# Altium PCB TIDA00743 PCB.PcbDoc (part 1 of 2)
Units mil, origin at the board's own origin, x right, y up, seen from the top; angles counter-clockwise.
Board outline 2110 x 1665 mil, 6 copper layers (Layer 1 - Top Layer, Layer 2 - GND, Layer 3 - Sensitive, Layer 4 - PWR, Layer 5 - GND, Layer 6 - Bottom Layer), stack 59.268 mil thick; 144 components, 87 nets, 420 pads, 309 vias.
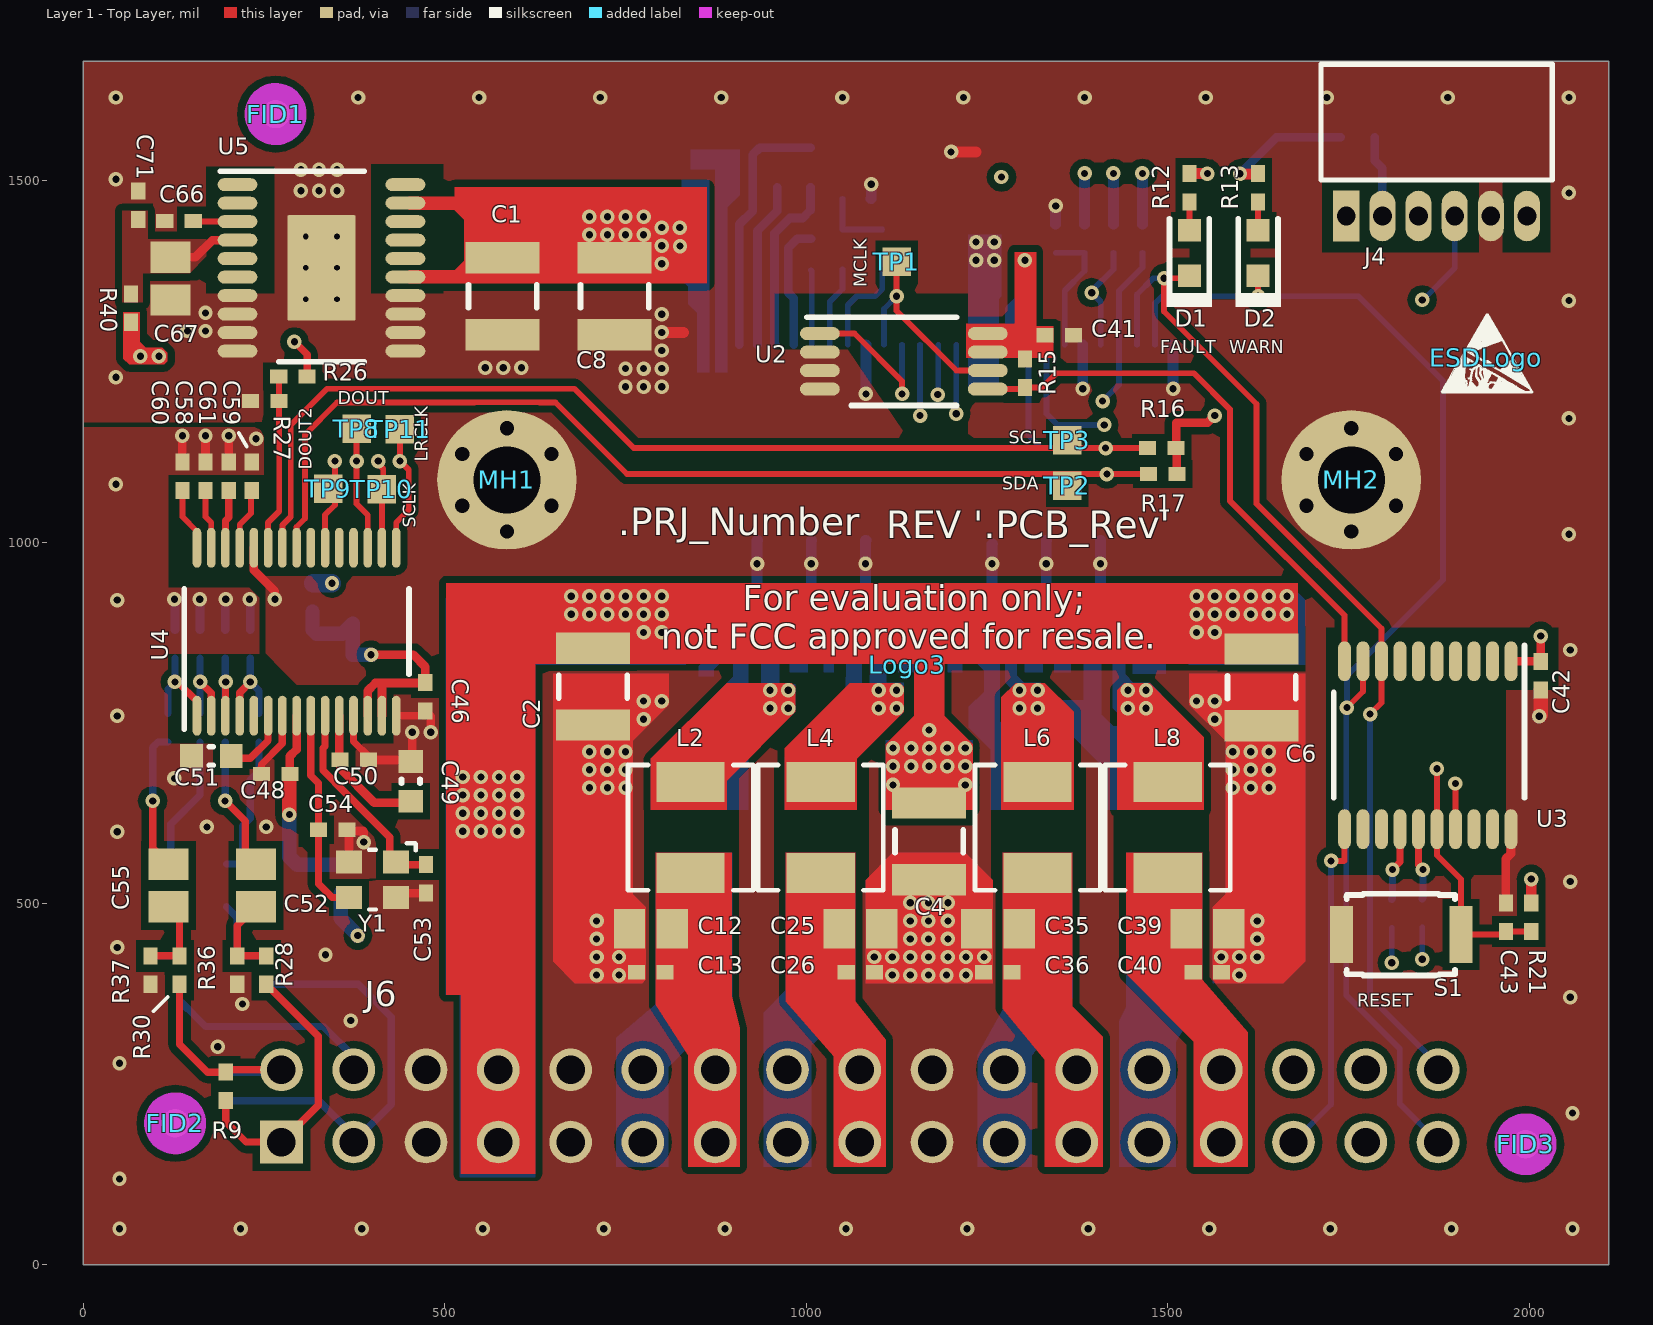
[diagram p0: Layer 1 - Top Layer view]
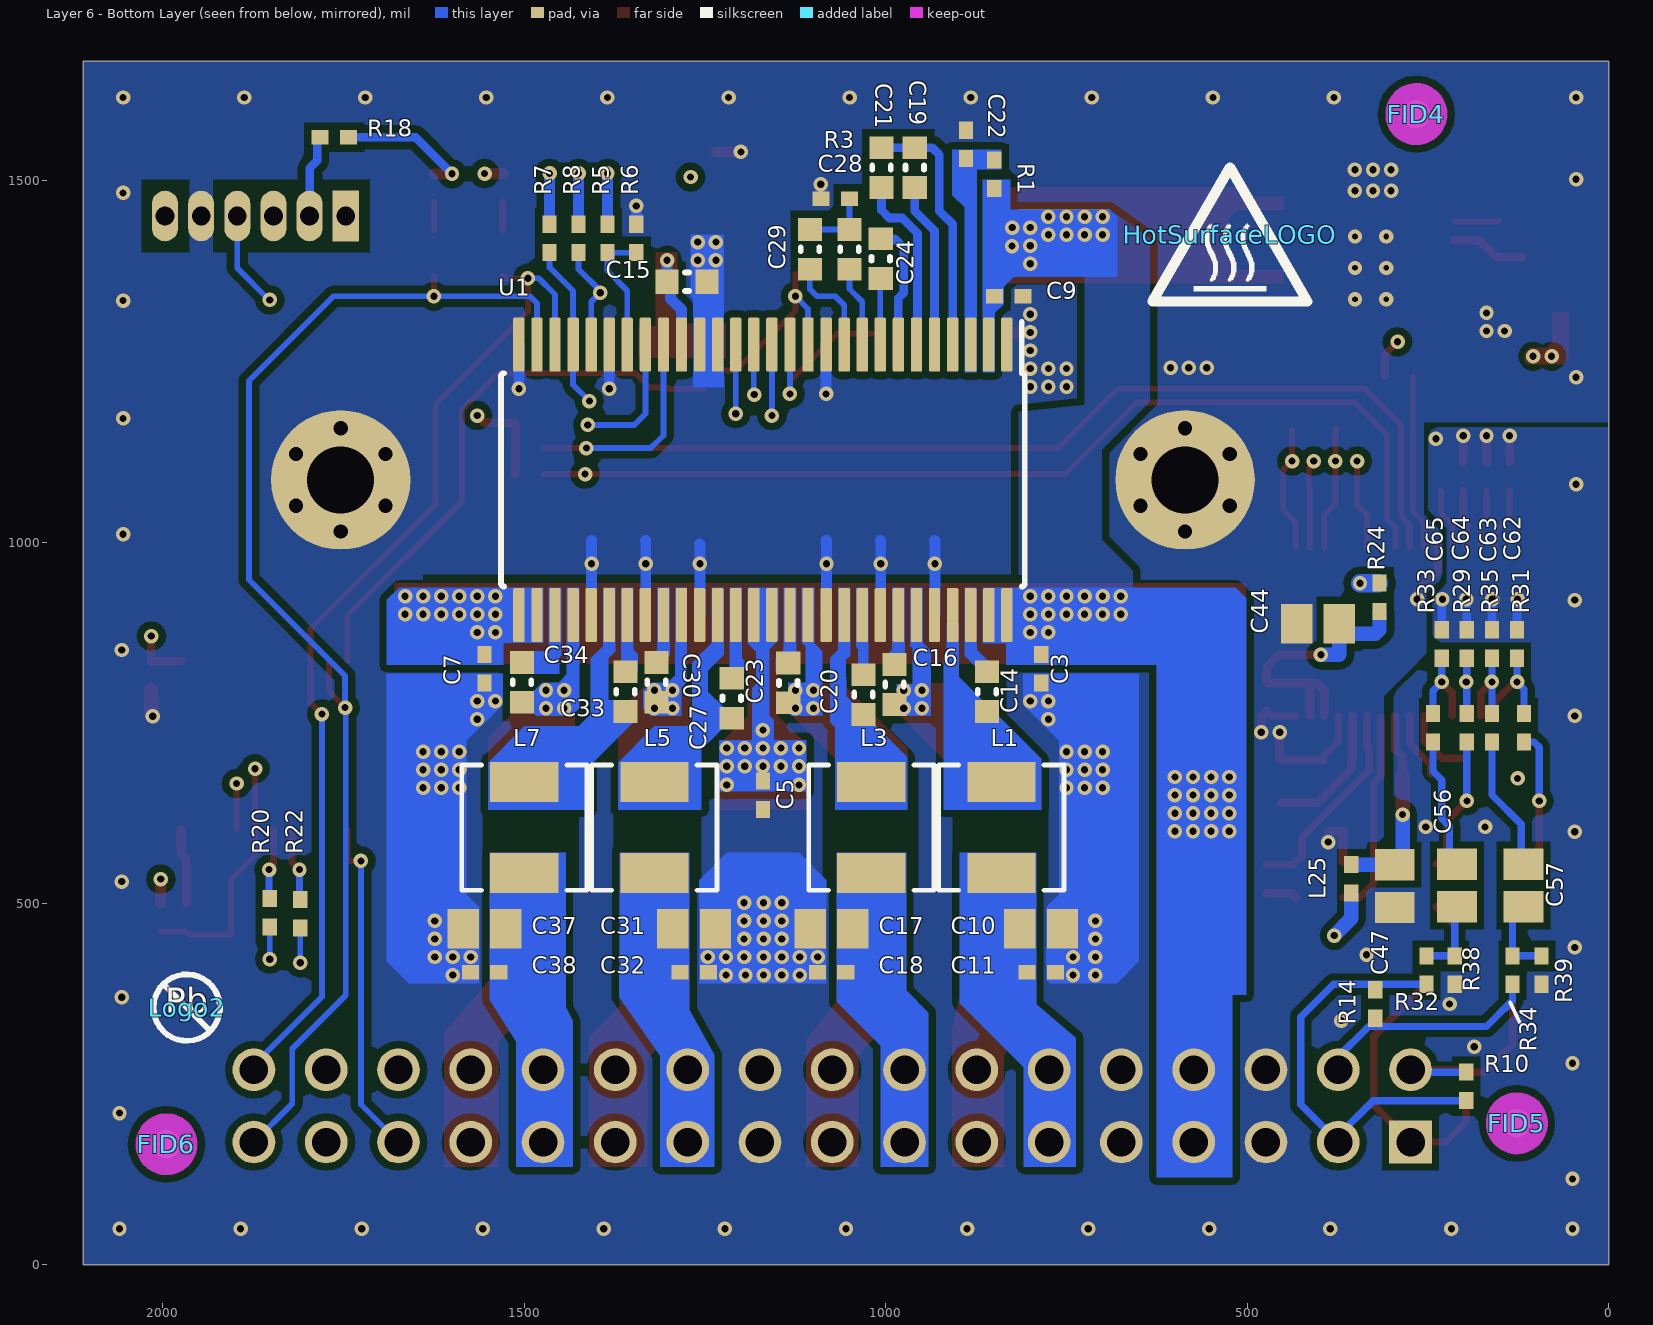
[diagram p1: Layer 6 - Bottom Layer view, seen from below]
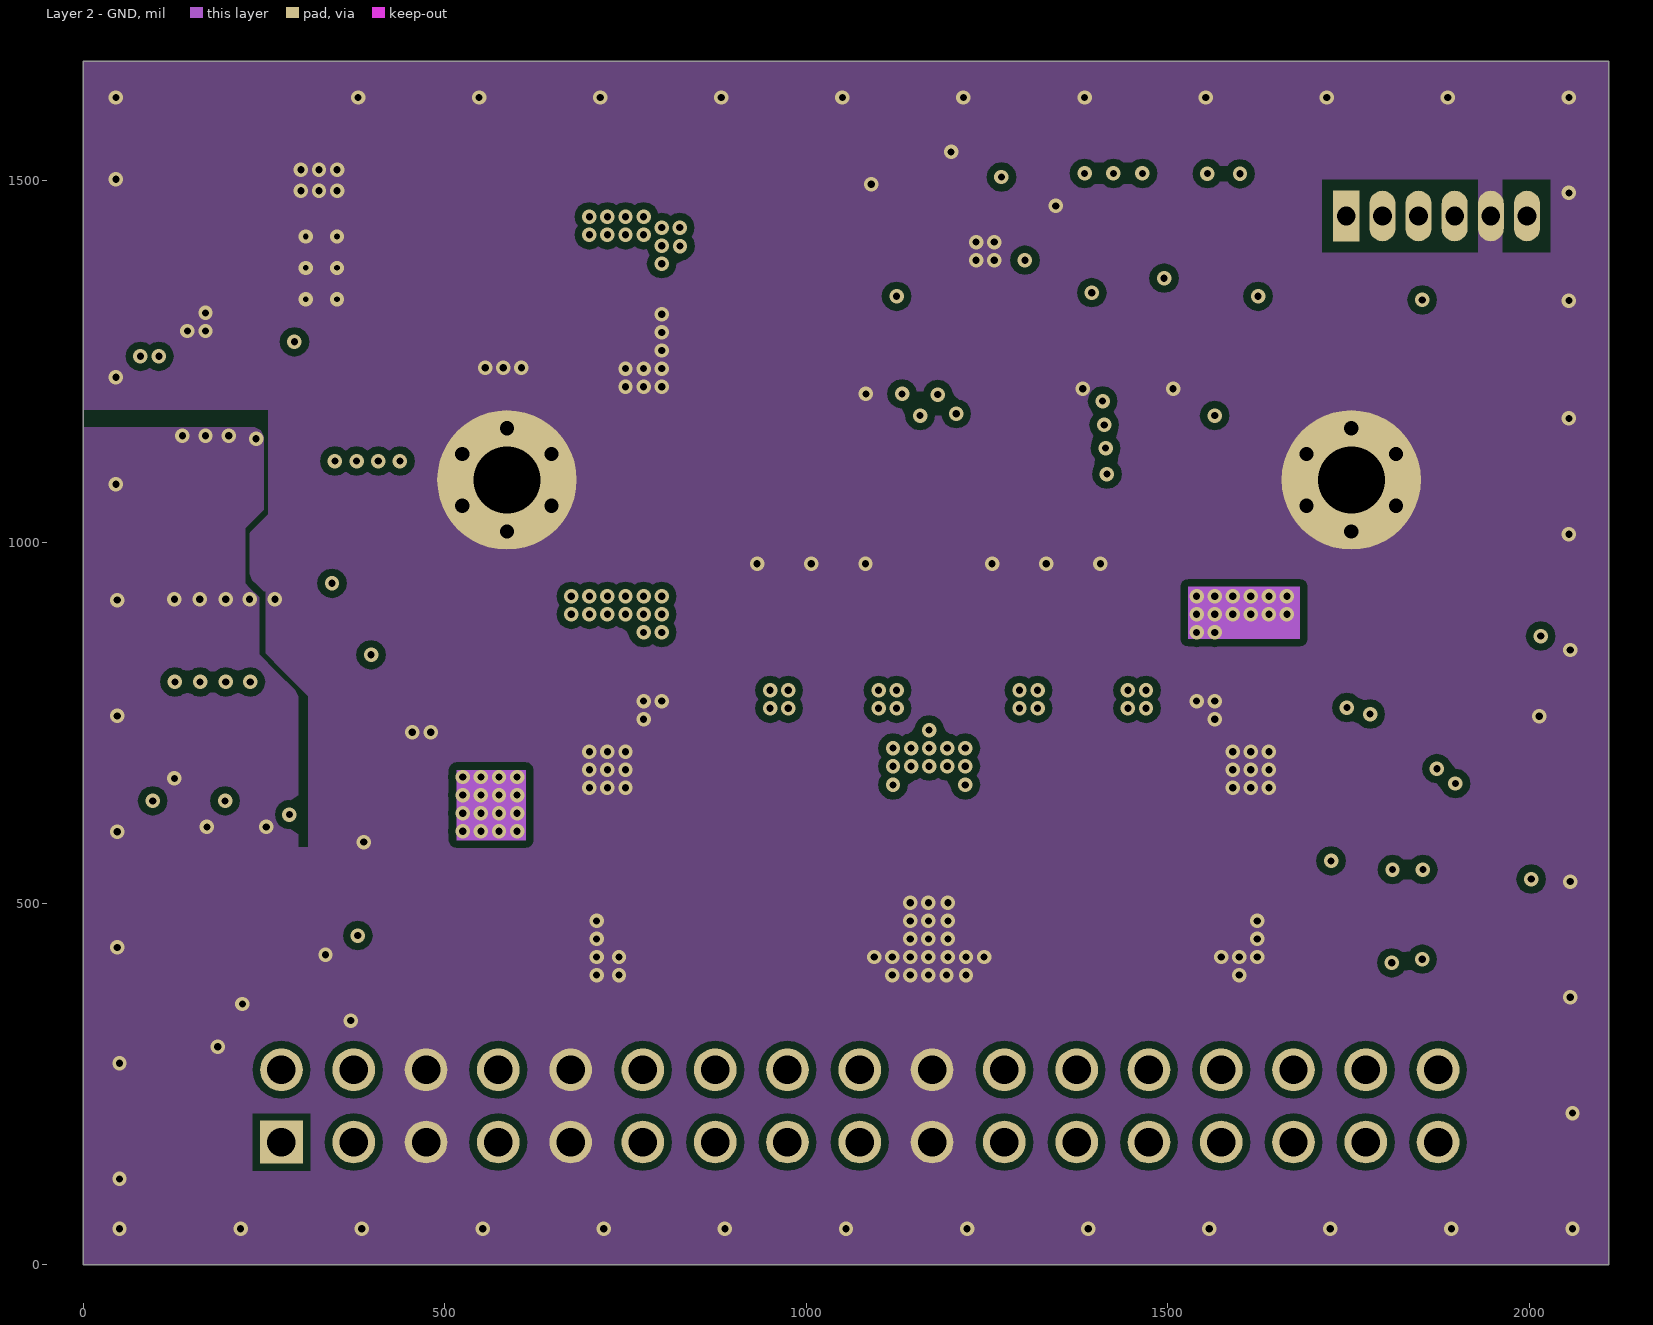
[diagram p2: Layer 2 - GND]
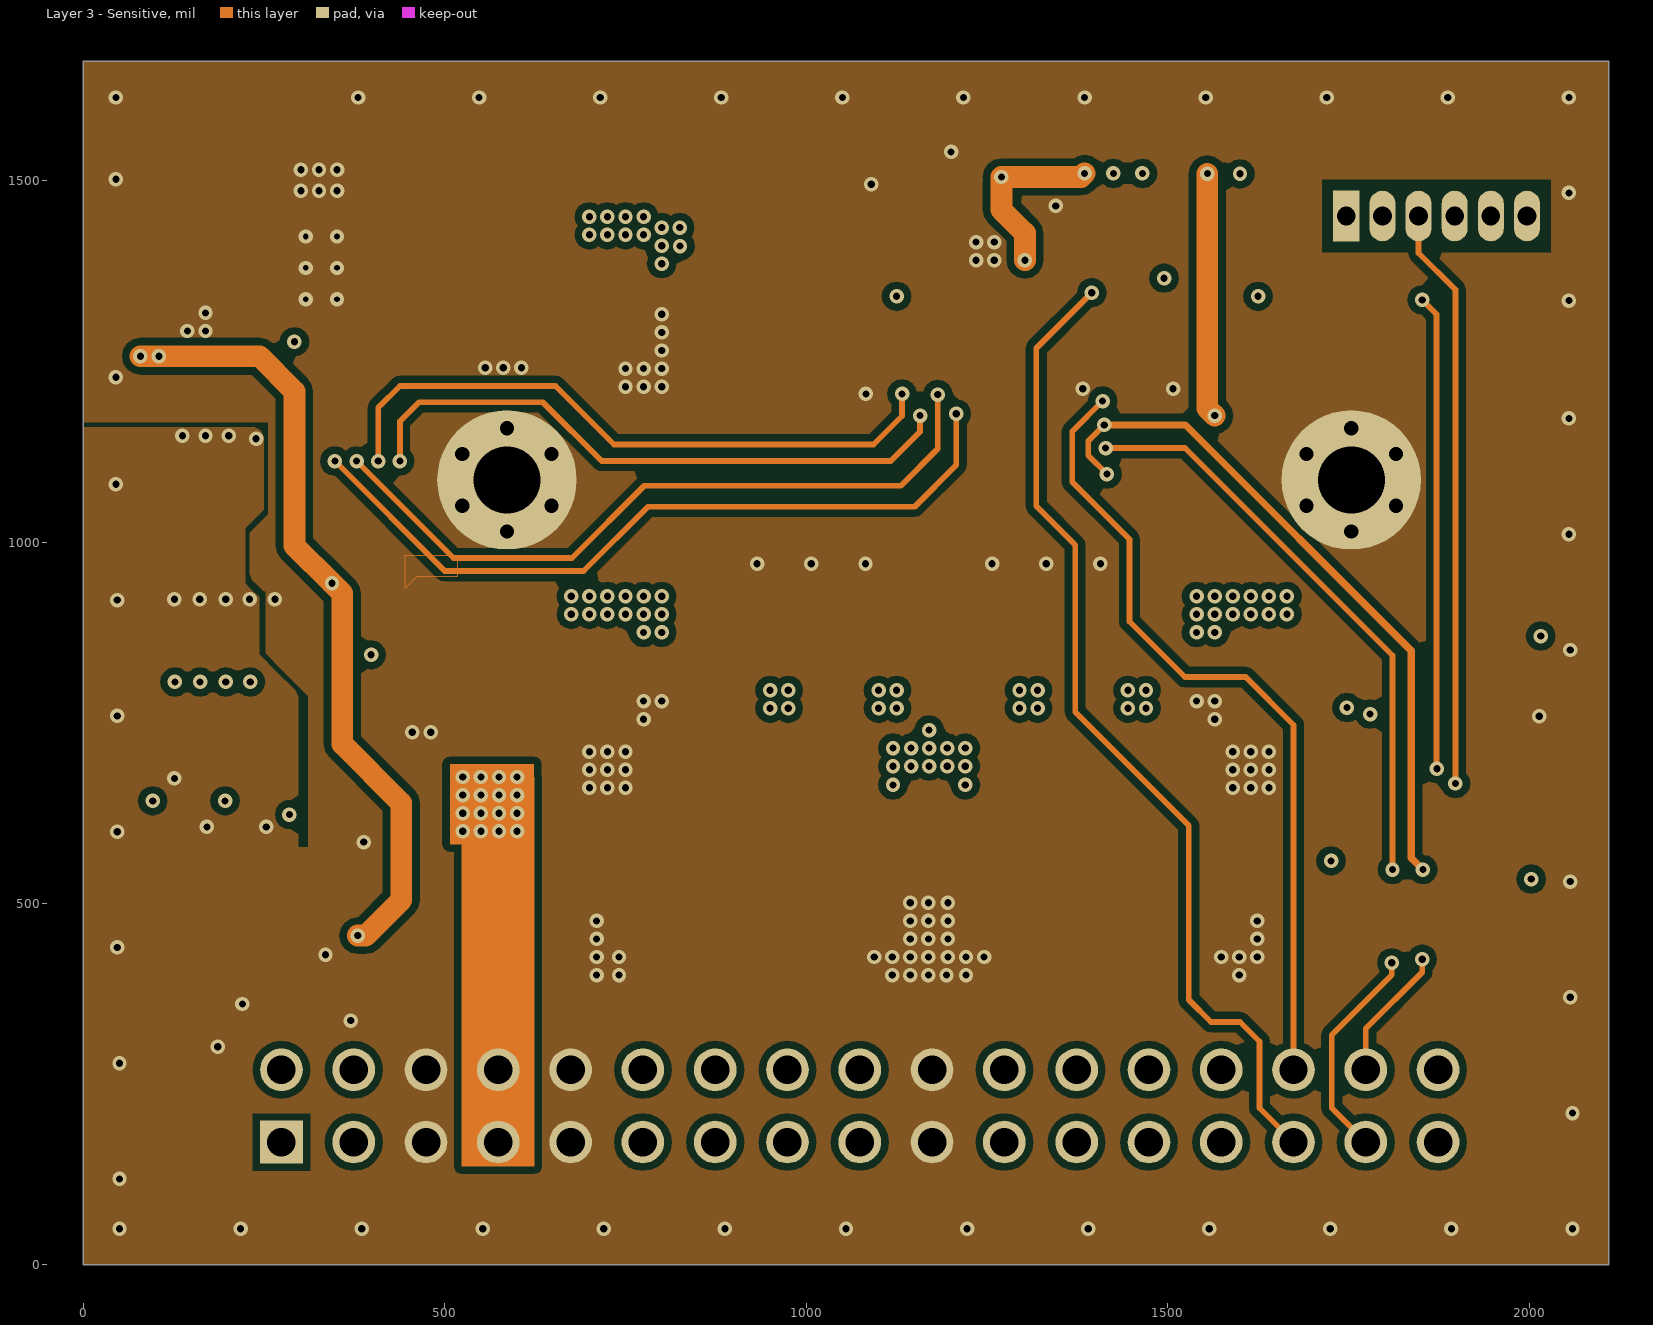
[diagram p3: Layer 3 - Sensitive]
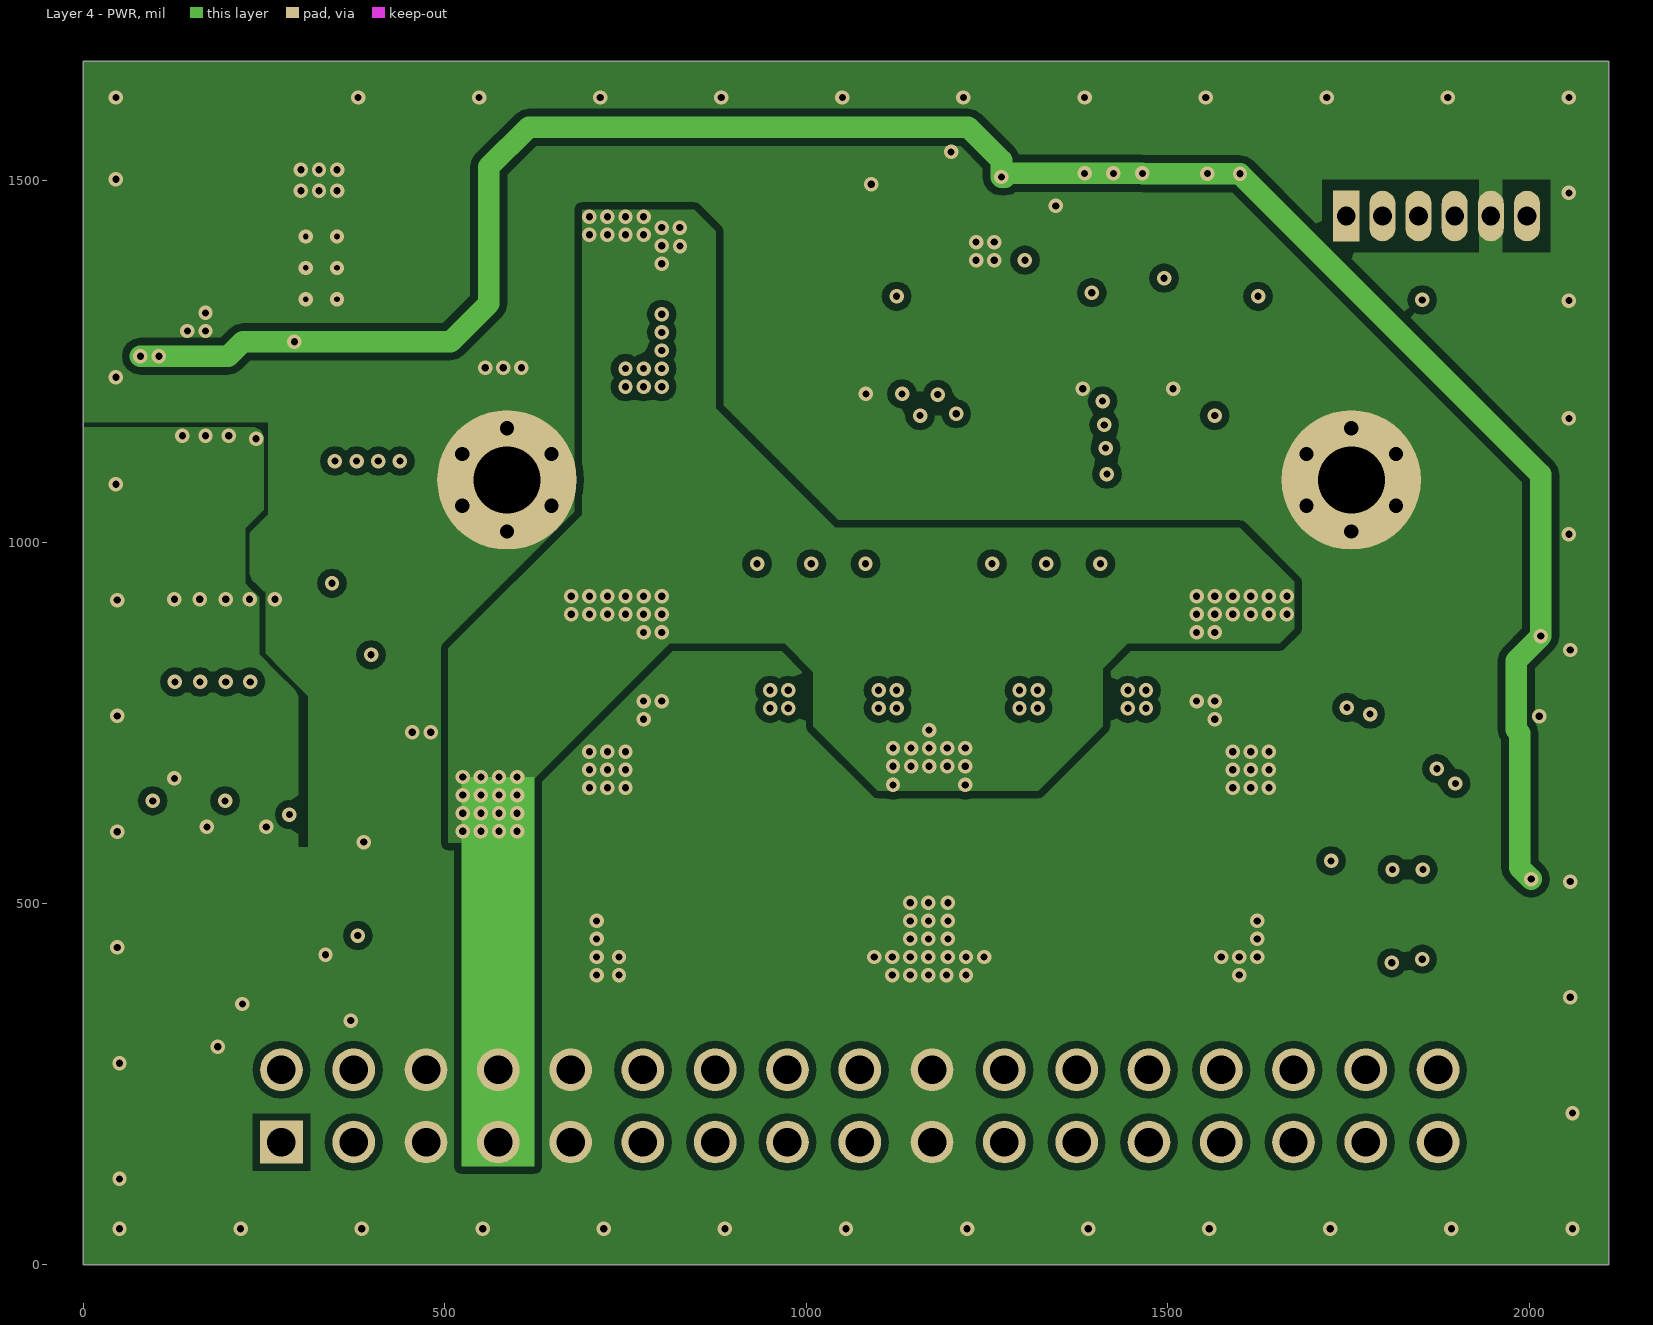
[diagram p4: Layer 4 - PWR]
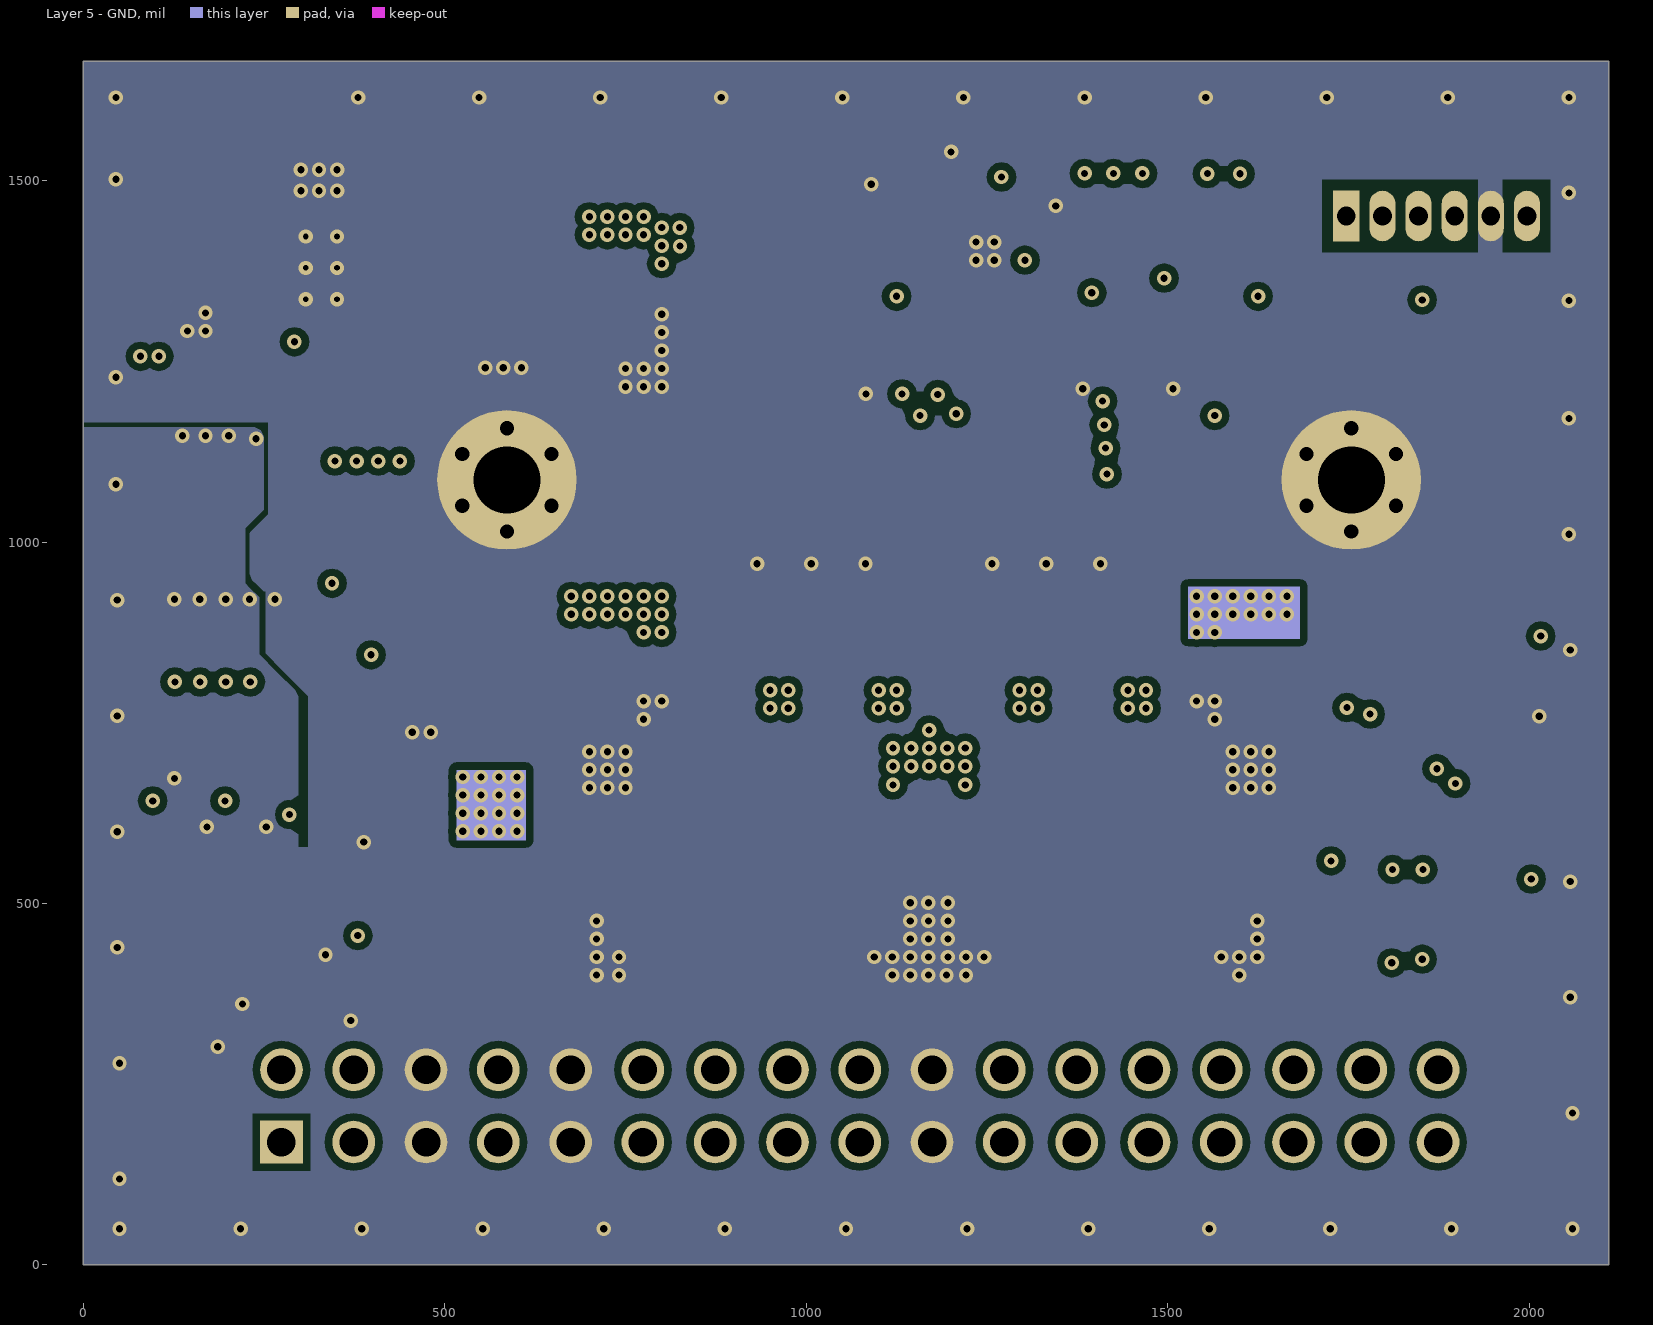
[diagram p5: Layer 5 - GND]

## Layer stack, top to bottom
Top Solder: solder mask 0.4, Solder Resist, Dk 3.5
Layer 1 - Top Layer: signal copper 1.4
Dielectric 1: prepreg 5.2, 370HR, Dk 4.2
Layer 2 - GND: signal copper 1.417
Dielectric 2: core 5.2, 370HR, Dk 4.2
Layer 3 - Sensitive: signal copper 1.417
Dielectric 3: prepreg 30, 370HR, Dk 4.2
Layer 4 - PWR: signal copper 1.417
Dielectric 4: core 5.2, 370HR, Dk 4.2
Layer 5 - GND: signal copper 1.417
Dielectric 5: prepreg 5.2, 370HR, Dk 4.2
Layer 6 - Bottom Layer: signal copper 1.4
Bottom Solder: solder mask 0.4, Solder Resist, Dk 3.5

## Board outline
0,0 2110,0 2110,1665 0,1665

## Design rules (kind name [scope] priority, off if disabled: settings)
AcuteAngle [All] p1: minimum=4.50000000000000E+0001 checktracksonly=FALSE
AssemblyTestPointUsage [All] p1: valid=2
Clearance Clearance_Keepouts [((IsTrack Or IsArc) And Not InPoly) And IsFree and IsKeepOut vs ((IsTrack Or IsArc) And Not InPoly) And IsFree and IsKeepOut] p1: gap=0
Clearance Clearance_Poly [InPolygon] p2: gap=10
Clearance [All] p3: gap=7
ComponentClearance ComponentClearance_MountingHoles_FiducialMarks [InComponentClass('Mounting Holes') vs InComponentClass('FiducialMark')] p1: gap=50 collisioncheckmode=3 verticalgap=10 showdistances=FALSE
ComponentClearance ComponentClearance_Shunt [InComponentClass('Header') vs InComponentClass('Shunt')] p2: gap=0 collisioncheckmode=3 verticalgap=0 showdistances=FALSE
ComponentClearance ComponentClearance_Logo [InComponentClass('Logo')] p3: gap=20 collisioncheckmode=3 verticalgap=10 showdistances=FALSE
ComponentClearance ComponentClearance_ScrewToNut [(HasFootprint('NY PMS 440 0025 PH')) vs (HasFootprint('Keystone_1902C'))] p4: gap=5 collisioncheckmode=3 verticalgap=10 showdistances=FALSE
ComponentClearance ComponentClearance_MountingHoles [InComponentClass('Mounting Holes')] p5: gap=75 collisioncheckmode=3 verticalgap=100000 showdistances=FALSE
ComponentClearance ComponentClearance_SmallPassives [HasFootprint('0201*') or HasFootprint('0402*') or HasFootprint('0508') or HasFootprint('0603*') or HasFootprint('0612') or HasFootprint('0805*') or HasFootprint('0815*') or HasFootprint('0830*') or HasFootprint('1206*') or HasFootprint('1210*') or HasFootprint('1808*') or HasFootprint('1812*') or HasFootprint('1825*') or HasFootprint('2010*') or HasFootprint('2220*') or HasFootprint('2225*') or HasFootprint('2512*') or HasFootprint('2728*') or HasFootprint('3518*') vs HasFootprint('0201*') or HasFootprint('0402*') or HasFootprint('0508') or HasFootprint('0603*') or HasFootprint('0612') or HasFootprint('0805*') or HasFootprint('0815*') or HasFootprint('0830*') or HasFootprint('1206*') or HasFootprint('1210*') or HasFootprint('1808*') or HasFootprint('1812*') or HasFootprint('1825*') or HasFootprint('2010*') or HasFootprint('2220*') or HasFootprint('2225*') or HasFootprint('2512*') or HasFootprint('2728*') or HasFootprint('3518*')] p6: gap=5 collisioncheckmode=3 verticalgap=10 showdistances=FALSE
ComponentClearance ComponentClearance_THtoSMT [IsThruComponent vs IsSMTComponent] p7: gap=15 collisioncheckmode=3 verticalgap=30 showdistances=FALSE
ComponentClearance ComponentClearance_THtoTH [IsThruComponent vs IsThruComponent] p8: gap=30 collisioncheckmode=3 verticalgap=30 showdistances=FALSE
ComponentClearance [All] p9: gap=10 collisioncheckmode=3 verticalgap=10 showdistances=FALSE
DiffPairsRouting [All] p1: maxlimit=100 minlimit=10 mostfreqgap=10 toplayer_minwidth=15 toplayer_maxwidth=15 toplayer_prefwidth=15 midlayer1_minwidth=15 midlayer1_maxwidth=15 midlayer1_prefwidth=15 midlayer2_minwidth=15 midlayer2_maxwidth=15 midlayer2_prefwidth=15 midlayer3_minwidth=15 midlayer3_maxwidth=15 midlayer3_prefwidth=15 midlayer4_minwidth=15 midlayer4_maxwidth=15 midlayer4_prefwidth=15 bottomlayer_minwidth=15 bottomlayer_maxwidth=15 bottomlayer_prefwidth=15 maxuncoupledlength=1000
FabricationTestPointUsage TestPointUsage [All] p1: valid=2 allowmultiple=FALSE
FabricationTestpoint Testpoint [All] p1: side=3 testpointundercomponent=TRUE minsize=40 maxsize=100 preferedsize=60 minholesize=0 maxholesize=40 preferedholesize=32 testpointgrid=1 allowsidetop=TRUE allowsidebottom=TRUE usegrid=TRUE gridtolerance=0.01
FanoutControl Fanout_LCC [IsLCC] p1: bgadir=Out bgaviamode=Centered fanoutstyle=Auto fanoutdirection=Alternating viagrid=1 // Fanout_LCC (Default Rule)
FanoutControl Fanout_BGA [IsBGA] p2: bgadir=Out bgaviamode=Centered fanoutstyle=Auto fanoutdirection=Alternating viagrid=1 // Fanout_BGA (Default Rule)
FanoutControl Fanout_Default [All] p4: bgadir=Out bgaviamode=Centered fanoutstyle=Auto fanoutdirection=Alternating viagrid=1 // Fanout_Default (Default Rule)
FanoutControl Fanout_Small [(CompPinCount < 5)] p5: bgadir=Out bgaviamode=Centered fanoutstyle=Auto fanoutdirection=OutThenIn viagrid=1 // Fanout_Small (Default Rule)
HoleSize [All] p1: absolutevalues=TRUE maxlimit=251 minlimit=7.87 maxpercent=80.000 minpercent=20.000
MinimumAnnularRing MinimumAnnularRing_ThermalPadVias [IsVia and InAnyComponent] p1: minimumring=5.91
MinimumAnnularRing [All] p2: minimumring=5
MinimumSolderMaskSliver MinimumSolderMaskSliver_Logo [InComponentClass('Logo') vs InComponentClass('Logo')] p1: minsoldermaskwidth=0.7
MinimumSolderMaskSliver [All] p2: minsoldermaskwidth=3.94
PlaneConnect [All] p1: planeconnectstyle=Relief reliefexpansion=10 reliefentries=4 reliefconductorwidth=10 reliefairgap=10
PolygonConnect [All] p1: connectstyle=Direct reliefconductorwidth=10 reliefentries=4 polygonreliefangle="90 Angle" airgapwidth=10
RoutingVias ThermalPadVias [IsVia and InAnyComponent] p1: holewidth=7.87 width=19.68 viastyle="Through Hole" minholewidth=7.87 minwidth=19.68 maxholewidth=20 maxwidth=40
RoutingVias [All] p2: holewidth=16 width=34 viastyle="Through Hole" minholewidth=7.87 minwidth=20 maxholewidth=40 maxwidth=65
SilkToBoardRegionClearance [Not ((IsComment or IsDesignator) And (Hide <> 'False')) and not InRegion(1000,500,4000,800)] p1:
SilkToSilkClearance SilkToSilkClearance_Pb-FreeLogo [(HasFootprint('Pb-Free_Overlay_Medium') OR HasFootprint('Pb-Free_Overlay_Small')) vs (HasFootprint('Pb-Free_Overlay_Medium') OR HasFootprint('Pb-Free_Overlay_Small'))] p1: silktosilkclearance=0
SilkToSilkClearance [All] p2: silktosilkclearance=4
SilkToSolderMaskClearance SilkToComponentPadClearance [IsPad and InAnycomponent] p1: minsilkscreentomaskgap=5 clearancetoexposedcopper=TRUE
SilkToSolderMaskClearance "Silk to Solder Mask Opening" [All] p2: minsilkscreentomaskgap=4 clearancetoexposedcopper=FALSE
SolderMaskExpansion [All] p1: expansion=1.97
Width [All] p1: maxlimit=100 minlimit=6 preferedwidth=10 checkconnectedcopper=TRUE
15 further rules are at their usual default settings.

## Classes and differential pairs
component class Header: J6
component class FiducialMark: FID1 FID2 FID3 FID4 FID5 FID6
component class AssemblyNote: ZZ1 ZZ2 ZZ3 ZZ4

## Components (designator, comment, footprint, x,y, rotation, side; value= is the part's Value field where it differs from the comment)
C1 "GRM32ER71H106KA12L" 1210L 580,1340 r270 top
C2 "GRM32ER71H106KA12L" 1210L 705,800 r270 top
C3 "C1005X7R1H104K050BB" 0402L 785,825 r270 bottom
C4 "GRM32ER71H106KA12L" 1210L 1170,586 r270 top
C5 "C1005X7R1H104K050BB" 0402L 1170,650 r270 bottom
C6 "GRM32ER71H106KA12L" 1210L 1630,799 r270 top
C7 "C1005X7R1H104K050BB" 0402L 1555,825 r270 bottom
C8 "GRM32ER71H106KA12L" 1210L 735,1340 r270 top
C9 "C1005X7R1H104K050BB" 0402L 830,1340 r180 bottom
C10 "GRM21BR71H105KA12L" 0805L 785,465 r180 bottom
C11 "GCM155R71H103KA55D" 0402L 785,405 r180 bottom
C12 "GRM21BR71H105KA12L" 0805L 785,465 r180 top
C13 "GCM155R71H103KA55D" 0402L 785,405 r180 top
C14 "C1608X7R1E105K080AB" 0603L 860,793 r90 bottom
C15 "C1608X7R1E105K080AB" 0603L 1275,1360 r180 bottom
C16 "C1608X7R1E105K080AB" 0603L 988,803 r90 bottom
C17 "GRM21BR71H105KA12L" 0805L 1075,465 r0 bottom
C18 "GCM155R71H103KA55D" 0402L 1075,405 r0 bottom
C19 "C1608X7R1E105K080AB" 0603L 960,1518 r90 bottom
C20 "C1608X7R1E105K080AB" 0603L 1031,789 r90 bottom
C21 "C1608X7R1E105K080AB" 0603L 1006,1518 r90 bottom
C22 "C1005X7R1H104K050BB" 0402L 889,1550 r90 bottom
C23 "C1608X7R1E105K080AB" 0603L 1135,805.2 r90 bottom
C24 "C1608X7R1E105K080AB" 0603L 1007,1392 r90 bottom
C25 "GRM21BR71H105KA12L" 0805L 1075,465 r0 top
C26 "GCM155R71H103KA55D" 0402L 1075,405 r0 top
C27 "C1608X7R1E105K080AB" 0603L 1213,784 r90 bottom
C28 "C1608X7R1E105K080AB" 0603L 1050,1405 r90 bottom
C29 "C1608X7R1E105K080AB" 0603L 1105,1405 r90 bottom
C30 "C1608X7R1E105K080AB" 0603L 1317,806 r90 bottom
C31 "GRM21BR71H105KA12L" 0805L 1265,465 r180 bottom
C32 "GCM155R71H103KA55D" 0402L 1265,405 r180 bottom
C33 "C1608X7R1E105K080AB" 0603L 1360,793 r90 bottom
C34 "C1608X7R1E105K080AB" 0603L 1503,806 r90 bottom
C35 "GRM21BR71H105KA12L" 0805L 1265,465 r180 top
C36 "GCM155R71H103KA55D" 0402L 1265,405 r180 top
C37 "GRM21BR71H105KA12L" 0805L 1555,465 r0 bottom
C38 "GCM155R71H103KA55D" 0402L 1555,405 r0 bottom
C39 "GRM21BR71H105KA12L" 0805L 1555,465 r0 top
C40 "GCM155R71H103KA55D" 0402L 1555,405 r0 top
C41 "C1005X7R1H104K050BB" 0402L 1350,1286 r0 top
C42 "C1005X7R1H104K050BB" 0402L 2016,815 r270 top
C43 "C1005X7R1H222K" 0402L 1967.81,481 r90 top
C44 "GRM21BR71A106KE51L" 0805L 402,887 r0 bottom
C46 "C1005X7R1H104K050BB" 0402L 473,786 r270 top
C47 "GRM21BR71A106KE51L" 0805L 296,524 r270 bottom
C48 "C1005X7R1H104K050BB" 0402L 266,679 r180 top
C49 "GCM188R70J225KE22D" 0603L 453,669 r90 top
C50 "C1005X7R1H104K050BB" 0402L 375,699 r0 top
C51 "GCM188R70J225KE22D" 0603L 177,704 r180 top
C52 "GRM21BR71A106KE51L" 0805L 239,525 r90 top
C53 "GRM1555C1H200JA01D" 0402L 474,534 r270 top
C54 "GRM1555C1H200JA01D" 0402L 345,602 r0 top
C55 "GRM21BR71A106KE51L" 0805L 118,525 r90 top
C56 "GRM21BR71A106KE51L" 0805L 210,525 r90 bottom
C57 "GRM21BR71A106KE51L" 0805L 118,525 r90 bottom
C58 "C1005X7R1H104K050BB" 0402L 169,1091 r90 top
C59 "C1005X7R1H104K050BB" 0402L 233,1091 r90 top
C60 "C1005X7R1H104K050BB" 0402L 137,1091 r90 top
C61 "C1005X7R1H104K050BB" 0402L 201,1091 r90 top
C62 "GCM155R71H103KA55D" 0402L 126.72,859 r90 bottom
C63 "GCM155R71H103KA55D" 0402L 161.48,859 r90 bottom
C64 "GCM155R71H103KA55D" 0402L 196.24,859 r90 bottom
C65 "GCM155R71H103KA55D" 0402L 231,859 r90 bottom
C66 "C1005X7R1H222K" 0402L 132.35,1444.31 r180 top
C67 "GRM21BR71A106KE51L" 0805L 120.35,1364.31 r270 top
C71 "C1005X7R1H104K050BB" 0402L 76,1466 r90 top
D1 "150060SS75000" WL-SMCW_RED 1530,1400 r90 top
D2 "150060YS75000" WL-SMCW_YELLOW 1625,1400 r90 top
ESDLogo "ESD Susceptible" ESD_Overlay_Small 1941,1255 r0 top
FID1 "Fiducial" Fiducial10-20 266,1592 r0 top
FID2 "Fiducial" Fiducial10-20 127,196 r0 top
FID3 "Fiducial" Fiducial10-20 1995,167 r0 top
FID4 "Fiducial" Fiducial10-20 266,1592 r180 bottom
FID5 "Fiducial" Fiducial10-20 127,196 r180 bottom
FID6 "Fiducial" Fiducial10-20 1995,167 r180 bottom
HotSurfaceLOGO "CAUTION HOT SURFACE" IEC_HotSurface_Small 524,1426 r180 bottom
J4 "851-43-006-20-001000" CONN_851-43-006-20-001000 1872,1451 r180 top
J6 "PRPC017DBAN-M71RC" Sullins_PRxC017DBAN-M71RC 1074.04,220 r90 top
L1 "FDSD0420-H-3R3M" FDSD0420 840,605 r270 bottom
L2 "FDSD0420-H-3R3M" FDSD0420 840,605 r270 top
L3 "FDSD0420-H-3R3M" FDSD0420 1020,605 r270 bottom
L4 "FDSD0420-H-3R3M" FDSD0420 1020,605 r270 top
L5 "FDSD0420-H-3R3M" FDSD0420 1320,605 r270 bottom
L6 "FDSD0420-H-3R3M" FDSD0420 1320,605 r270 top
L7 "FDSD0420-H-3R3M" FDSD0420 1500,605 r270 bottom
L8 "FDSD0420-H-3R3M" FDSD0420 1500,605 r270 top
L25 "BLM15HG102SN1D" 0402L 356,534 r270 bottom
Logo2 "Pb-Free Symbol" Pb-Free_Overlay_Small 1967,356 r180 bottom
Logo3 "FCC disclaimer" FCC_disclaimer_stacked 1139.69,830 r0 top
MH1 "MTG_Pads" MTGP_2-48_PanHead 586,1086 r0 top
MH2 "MTG_Pads" MTGP_2-48_PanHead 1754,1086 r0 top
R1 "CRCW04020000Z0ED" 0402L 850,1509 r90 bottom
R3 "CRCW04020000Z0ED" 0402L 1070,1475 r180 bottom
R5 "CRCW0402100KFKED" 0402L 1385,1420 r270 bottom
R6 "CRCW04024K99FKED" 0402L 1345,1420 r90 bottom
R7 "CRCW040210K0FKED" 0402L 1465,1420 r90 bottom
R8 "CRCW040210K0FKED" 0402L 1425,1420 r90 bottom
R9 "CRCW04020000Z0ED" 0402L 197,247 r90 top
R10 "CRCW04020000Z0ED" 0402L 197,247 r90 bottom
R12 "CRCW04021K00FKED" 0402L 1530,1490 r270 top
R13 "CRCW04021K00FKED" 0402L 1625,1490 r270 top
R14 "CRCW04020000Z0ED" 0402L 323,361 r90 bottom
R15 "CRCW040210K0FKED" 0402L 1302.48,1233.44 r90 top
R16 "CRCW04024K99FKED" 0402L 1492,1130 r0 top
R17 "CRCW04024K99FKED" 0402L 1493,1094 r0 top
R18 "CRCW04020000Z0ED" 0402L 1763,1560 r180 bottom
R20 "CRCW04020000Z0ED" 0402L 1852,487 r90 bottom
R21 "CRCW040247K5FKED" 0402L 2002.81,481 r90 top
R22 "CRCW04020000Z0ED" 0402L 1810,486.1 r90 bottom
R24 "CRCW04020000Z0ED" 0402L 317,923.53 r90 bottom
R26 "CRCW040210K0FKED" 0402L 290,1229 r0 top
R27 "CRCW040210K0FKED" 0402L 251,1195 r0 top
R28 "CRCW04020000Z0ED" 0402L 253,408 r270 top
R29 "CRCW0402100RFKED" 0402L 196.24,743 r90 bottom
R30 "CRCW04020000Z0ED" 0402L 133,408 r270 top
R31 "CRCW0402100RFKED" 0402L 117,743 r90 bottom
R32 "CRCW04020000Z0ED" 0402L 252,408 r270 bottom
R33 "CRCW0402100RFKED" 0402L 243,743 r90 bottom
R34 "CRCW04020000Z0ED" 0402L 133,408 r270 bottom
R35 "CRCW0402100RFKED" 0402L 161.48,743 r90 bottom
R36 "CRCW0402100KFKED" 0402L 213,408 r90 top
R37 "CRCW0402100KFKED" 0402L 93,408 r90 top
R38 "CRCW0402100KFKED" 0402L 213,408 r90 bottom
R39 "CRCW0402100KFKED" 0402L 93,408 r90 bottom
R40 "CRCW04020000Z0ED" 0402L 66,1323.74 r90 top
S1 "SKRKAEE010" SW_SKRKAEE010 1823,457 r180 top
TP1 "TESTPOINT" PAD_1MM_SQUARE 1125,1388 r180 top
TP2 "TESTPOINT" PAD_1MM_SQUARE 1361,1078 r270 top
TP3 "TESTPOINT" PAD_1MM_SQUARE 1361,1141 r270 top
TP8 "TESTPOINT" PAD_1MM_SQUARE 378,1157 r0 top
TP9 "TESTPOINT" PAD_1MM_SQUARE 339,1074 r0 top
TP10 "TESTPOINT" PAD_1MM_SQUARE 413.11,1073.11 r0 top
TP11 "TESTPOINT" PAD_1MM_SQUARE 438,1156 r0 top
U1 "TAS6424QDKQRQ1" DKQ0056A 1170,1086 r270 bottom locked
U2 "CDCS504TPWRQ1" PW0008A_N 1135,1250 r0 top
U3 "MSP430G2332QPW2REP" PW0020A_N 1859.69,719 r270 top
U4 "PCM1865QDBTRQ1" DBT0030A_N 295,876 r90 top locked
U5 "TPS7B6733QPWPRQ1" PWP0020D_N 329.35,1379.31 r0 top
Y1 "ABM10-24.576MHZ-E20-T" XTAL_ABM10 400,533 r270 top
ZZ1 "This Assembly Note is for PCB labels only" AssemblyNoteLabel -100,2600 r0 top
ZZ2 "These assemblies are ESD sensitive, ESD precautions shall be observed." AssemblyNote -100,2500 r0 top
ZZ3 "These assemblies must be clean and free from flux and all contaminants. Use of no clean flux is not acceptable." AssemblyNote -100,2400 r0 top
ZZ4 "These assemblies must comply with workmanship standards IPC-A-610 Class 2, unless otherwise specified." AssemblyNote -100,2300 r0 top

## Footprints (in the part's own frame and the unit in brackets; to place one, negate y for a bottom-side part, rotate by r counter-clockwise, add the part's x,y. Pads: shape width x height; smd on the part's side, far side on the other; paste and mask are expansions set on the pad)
0402L [mm] "0402 from SM-752 data"
  rect 0.6x0.5 smd: 1(-0.5,0) 2(0.5,0)
  body extent -0.55,-0.3 0.55,0.3, height 0.6
0603L [mm] "0603 from SM-752 data"
  rect 0.8x0.85 smd: 1(-0.7,0) 2(0.7,0)
  silkscreen extent -0.07,-0.33 0.07,0.33, body extent -0.87,-0.47 0.87,0.47, height 1
0805L [mm] "0805 from SM-752 data"
  rect 1.1x1.4 smd: 1(-0.75,0) 2(0.75,0)
  body extent -1.1,-0.72 1.1,0.72, height 1.45
1210L [mm] "1210 from SM-752 data"
  rect 1.1x2.6 smd: 1(-1.35,0) 2(1.35,0)
  silkscreen extent -0.4,-1.2 0.4,1.2, body extent -1.7,-1.35 1.7,1.35, height 1.35
AssemblyNote [mil] "Assembly Note"
AssemblyNoteLabel [mil] "Assembly Note for PCB Labels"
CONN_851-43-006-20-001000 [mil] "Mill-Max"
  rect 36x70 hole 26: 1(125,0)
  oval 36x70 hole 26: 2(75,0) 3(25,0) 4(-25,0) 5(-75,0) 6(-125,0)
  silkscreen extent -160,-210 160,-50, body extent -157,-210 157,8, height 87
DBT0030A_N [mm] "TSSOP, 30-Leads, Body 7.8x4.4mm, Pitch 0.5mm, IPC Medium Density"
  oval 1.4x0.3 smd: 1(-2.95,3.5) 2(-2.95,3) 3(-2.95,2.5) 4(-2.95,2) 5(-2.95,1.5) 6(-2.95,1) 7(-2.95,0.5) 8(-2.95,0) 9(-2.95,-0.5) 10(-2.95,-1) 11(-2.95,-1.5) 12(-2.95,-2) 13(-2.95,-2.5) 14(-2.95,-3) 15(-2.95,-3.5) 16(2.95,-3.5) 17(2.95,-3) 18(2.95,-2.5) 19(2.95,-2) 20(2.95,-1.5) 21(2.95,-1) 22(2.95,-0.5) 23(2.95,0) 24(2.95,0.5) 25(2.95,1) 26(2.95,1.5) 27(2.95,2) 28(2.95,2.5) 29(2.95,3) 30(2.95,3.5)
  silkscreen extent -3.42,-3.95 1.5,3.95, body extent -3.21,-3.9 3.21,3.9, height 1.2
DKQ0056A [mm] "SOP, 56-Leads, Body 18.415x7.49mm, Pitch 0.635mm"
  rrect25% 1.9x0.4 smd: 1(-4.75,8.573) 2(-4.75,7.938) 3(-4.75,7.303) 4(-4.75,6.668) 5(-4.75,6.033) 6(-4.75,5.398) 7(-4.75,4.763) 8(-4.75,4.128) 9(-4.75,3.493) 10(-4.75,2.858) 11(-4.75,2.223) 12(-4.75,1.588) 13(-4.75,0.953) 14(-4.75,0.318) 15(-4.75,-0.317) 16(-4.75,-0.952) 17(-4.75,-1.587) 18(-4.75,-2.222) 19(-4.75,-2.857) 20(-4.75,-3.492) 21(-4.75,-4.127) 22(-4.75,-4.762) 23(-4.75,-5.397) 24(-4.75,-6.032) 25(-4.75,-6.667) 26(-4.75,-7.302) 27(-4.75,-7.937) 28(-4.75,-8.572) 29(4.75,-8.573) 30(4.75,-7.938) 31(4.75,-7.303) 32(4.75,-6.668) 33(4.75,-6.033) 34(4.75,-5.398) 35(4.75,-4.763) 36(4.75,-4.128) 37(4.75,-3.493) 38(4.75,-2.858) 39(4.75,-2.223) 40(4.75,-1.588) 41(4.75,-0.953) 42(4.75,-0.318) 43(4.75,0.317) 44(4.75,0.952) 45(4.75,1.587) 46(4.75,2.222) 47(4.75,2.857) 48(4.75,3.492) 49(4.75,4.127) 50(4.75,4.762) 51(4.75,5.397) 52(4.75,6.032) 53(4.75,6.667) 54(4.75,7.302) 55(4.75,7.937) 56(4.75,8.572)
  silkscreen extent -5.55,-9.2 3.74,9.2, body extent -5.18,-9.21 5.17,9.21, height 2.32
ESD_Overlay_Small [mil]
  silkscreen extent -62,-48 64,61
FCC_disclaimer_stacked [mil]
FDSD0420 [mm] "SMD, 2-Leads, Body 4.2x4.2mm"
  rect 1.4x2.4 smd: 1(-1.6,0) 2(1.6,0)
  silkscreen extent -2.2,-2.2 2.2,2.2, body extent -2.1,-2.1 2.1,2.1, height 2
Fiducial10-20 [mm]
  round 1 smd mask+0.5: 1(0,0)
  Layer 1 - Top Layer keep-out circle w1.178: c0,0 r0.5
IEC_HotSurface_Small [mil]
  silkscreen extent -107,-93 107,92
MTGP_2-48_PanHead [mm] "2-48 Mounting Hole, Plated, for Pan Head"
  round 4.9 hole 2.35: 1(0,0)
PAD_1MM_SQUARE [mm]
  rect 1x1 smd: 1(0,0)
Pb-Free_Overlay_Small [mil]
  silkscreen extent -46,-46 46,46
PW0008A_N [mm] "TSOP, 8-Leads, Body 3x4.4mm, Pitch 0.65mm, IPC Medium Density"
  oval 1.4x0.45 smd: 1(-2.95,0.975) 2(-2.95,0.325) 3(-2.95,-0.325) 4(-2.95,-0.975) 5(2.95,-0.975) 6(2.95,-0.325) 7(2.95,0.325) 8(2.95,0.975)
  silkscreen extent -3.4,-1.55 1.85,1.55, body extent -3.21,-1.5 3.21,1.5, height 1.2
PW0020A_N [mm] "TSOP, 20-Leads, Body 6.5x4.4mm, Pitch 0.65mm, IPC Medium Density"
  oval 1.4x0.45 smd: 1(-2.95,2.925) 2(-2.95,2.275) 3(-2.95,1.625) 4(-2.95,0.975) 5(-2.95,0.325) 6(-2.95,-0.325) 7(-2.95,-0.975) 8(-2.95,-1.625) 9(-2.95,-2.275) 10(-2.95,-2.925) 11(2.95,-2.925) 12(2.95,-2.275) 13(2.95,-1.625) 14(2.95,-0.975) 15(2.95,-0.325) 16(2.95,0.325) 17(2.95,0.975) 18(2.95,1.625) 19(2.95,2.275) 20(2.95,2.925)
  silkscreen extent -3.5,-3.3 1.85,3.4, body extent -3.21,-3.25 3.21,3.25, height 1
PWP0020D_N [mm] "SOP, 20-Leads, Body 6.4x4.4mm, Pitch 0.65mm, Thermal Pad 2x3mm, IPC Medium Density"
  rrect100% 1.4x0.45 smd: 1(-2.95,2.925) 2(-2.95,2.275) 3(-2.95,1.625) 4(-2.95,0.975) 5(-2.95,0.325) 6(-2.95,-0.325) 7(-2.95,-0.975) 8(-2.95,-1.625) 9(-2.95,-2.275) 10(-2.95,-2.925) 11(2.95,-2.925) 12(2.95,-2.275) 13(2.95,-1.625) 14(2.95,-0.975) 15(2.95,-0.325) 16(2.95,0.325) 17(2.95,0.975) 18(2.95,1.625) 19(2.95,2.275) 20(2.95,2.925)
  rrect4% 2.4x3.7 smd: 21(0,0)
  silkscreen extent -3.55,-3.3 1.5,3.4, body extent -3.21,-3.25 3.21,3.25, height 1
Sullins_PRxC017DBAN-M71RC [mm] "Header, 2.54mm, 17x2, R/A, TH"
  rect 1.5x1.5 hole 1: 1(-1.27,20.32)
  round 1.5 hole 1: 2(1.27,20.32) 3(-1.27,17.78) 4(1.27,17.78) 5(-1.27,15.24) 6(1.27,15.24) 7(-1.27,12.7) 8(1.27,12.7) 9(-1.27,10.16) 10(1.27,10.16) 11(-1.27,7.62) 12(1.27,7.62) 13(-1.27,5.08) 14(1.27,5.08) 15(-1.27,2.54) 16(1.27,2.54) 17(-1.27,0) 18(1.27,0) 19(-1.27,-2.54) 20(1.27,-2.54) 21(-1.27,-5.08) 22(1.27,-5.08) 23(-1.27,-7.62) 24(1.27,-7.62) 25(-1.27,-10.16) 26(1.27,-10.16) 27(-1.27,-12.7) 28(1.27,-12.7) 29(-1.27,-15.24) 30(1.27,-15.24) 31(-1.27,-17.78) 32(1.27,-17.78) 33(-1.27,-20.32) 34(1.27,-20.32)
  body extent -11.13,-21.59 1.59,21.59, height 5
SW_SKRKAEE010 [mm] "Alps recommended land pattern"
  rect 0.8x2 smd: 1(-2.1,0) 2(2.1,0)
  silkscreen extent -1.9,-1.44 1.92,1.44, body extent -2.4,-1.45 2.4,1.45, height 1.96
WL-SMCW_RED [mm] "WURTH"
  rect 0.8x0.8 smd: 1(-0.8,0) 2(0.8,0)
  silkscreen extent -1.9,-0.8 1.2,0.8, body extent -0.85,-0.45 0.85,0.45, height 0.8
WL-SMCW_YELLOW [mm] "WURTH"
  rect 0.8x0.8 smd: 1(-0.8,0) 2(0.8,0)
  silkscreen extent -1.9,-0.8 1.2,0.8, body extent -0.85,-0.45 0.85,0.45, height 0.8
XTAL_ABM10 [mm] "ABRACON"
  rect 0.8x0.9 smd: 1(-0.625,0.825) 2(-0.625,-0.825) 3(0.625,-0.825) 4(0.625,0.825)
  silkscreen extent -1.28,-0.13 1.05,1.52, body extent -1.05,-1.3 1.05,1.3, height 0.7

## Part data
C1 C2 C4 C6 C8: "CAP, CERM, 10 µF, 50 V, +/- 10%, X7R, 1210"
C3 C5 C7 C9 C22 C41 C42 C46 C48 C50 C58 C59 C60 C61 C71: "CAP, CERM, 0.1 µF, 50 V, +/- 10%, X7R, 0402"
C10 C12 C17 C25 C31 C35 C37 C39: "CAP, CERM, 1 µF, 50 V, +/- 10%, X7R, 0805"
C11 C13 C18 C26 C32 C36 C38 C40 C62 C63 C64 C65: "CAP, CERM, 0.01 µF, 50 V, +/- 10%, C0G/NP0, 0402"
C14 C15 C16 C19 C20 C21 C23 C24 C27 C28 C29 C30 C33 C34: "CAP, CERM, 1 µF, 25 V, +/- 10%, X7R, 0603"
C43 C66: "CAP, CERM, 2200 pF, 50 V, +/- 10%, X7R, 0402"
C44 C47 C52 C55 C56 C57 C67: "CAP, CERM, 10 µF, 10 V, +/- 10%, X7R, 0805"
C49 C51: "CAP, CERM, 2.2 µF, 6.3 V, +/- 10%, X7R, AEC-Q200 Grade 1, 0603"
C53 C54: "CAP, CERM, 20 pF, 50 V, +/- 5%, C0G/NP0, 0402"
D1: "LED, Super Red, SMD"
D2: "LED, Yellow, SMD"
ESDLogo: library part ESD_Susceptible, "ESD Susceptible Symbol"
FID1 FID2 FID3 FID4 FID5 FID6: "Fiducial mark.  There is nothing to buy or mount."
HotSurfaceLOGO: library part IEC_HotSurface, "IEC 61010-1 Hot Surface Warning"
J4: "Receptacle, 50mil, 6x1, R/A, TH"
J6: "Header, 2.54mm, 17x2, Gold, R/A, TH"
L1 L2 L3 L4 L5 L6 L7 L8: "Inductor, Shielded, Powdered Iron, 3.3 µH, 3.4 A, 0.059 ohm, SMD"
L25: "Ferrite Bead, 1000 ohm @ 100 MHz, 0.25 A, 0402"
Logo2: library part Pb-Free
Logo3: library part FCC_disclaimer, "FCC_disclaimer"
MH1 MH2: library part "Mounting Hole (Imperial) with Pads", "PCB Mounting Hole"
R1 R3 R9 R10 R14 R18 R20 R22 R24 R28 R30 R32 R34 R40: "RES, 0, 5%, 0.063 W, 0402"
R5 R36 R37 R38 R39: "RES, 100 k, 1%, 0.063 W, 0402"
R6 R16 R17: "RES, 4.99 k, 1%, 0.063 W, 0402"
R7 R8 R15 R26 R27: "RES, 10.0 k, 1%, 0.063 W, 0402"
R12 R13: "RES, 1.00 k, 1%, 0.063 W, 0402"
R21: "RES, 47.5 k, 1%, 0.063 W, 0402"
R29 R31 R33 R35: "RES, 100, 1%, 0.063 W, 0402"
S1: "Switch, Push Button, SMD"
TP1 TP2 TP3 TP8 TP9 TP10 TP11: library part PAD_1MM_SQUARE, "1.0x1.0mm pad, square, SMD"
U1: "Four-Channel Digital Input Automotive Digital Amplifier, DKQ0056A"
U2: "Clock Buffer/Clock Multiplier, PW0008A (TSSOP-8)"
U3: "MIXED SIGNAL MICROCONTROLLER, PW0020A"
U4: "110 dB 4ch Audio ADCs With Universal Front End, DBT0030A"
U5: "Automotive 450-mA High-Voltage Ultra-Low IQ Low-Dropout Regulator, PWP0020D (TSSOP-20)"
Y1: "Crystal, 24.576MHz, 10pF, SMD"
ZZ1: library part AssemblyNoteLabel
ZZ2 ZZ3 ZZ4: library part AssemblyNote

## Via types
v1: diameter 20, hole 10, Layer 1 - Top Layer to Layer 6 - Bottom Layer, tented both sides, 287 vias
v2: diameter 39.37, hole 19.68, Layer 1 - Top Layer to Layer 6 - Bottom Layer, 12 vias
v3: diameter 19.68, hole 7.87, Layer 1 - Top Layer to Layer 6 - Bottom Layer, 6 vias
v4: diameter 20, hole 10, Layer 1 - Top Layer to Layer 6 - Bottom Layer, tented bottom, 4 vias

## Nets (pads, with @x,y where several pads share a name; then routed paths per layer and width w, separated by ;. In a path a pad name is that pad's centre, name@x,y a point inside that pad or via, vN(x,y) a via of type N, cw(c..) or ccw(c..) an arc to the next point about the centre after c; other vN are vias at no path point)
1L: C64.1 R29.2 U4.3 | length 123.2
  Layer 1 - Top Layer w10: U4.3@196.57,759.86 v1@196.57,806.05 ; v1@197,806.05 v1(197,806.48)
  Layer 6 - Bottom Layer w10: R29.2@196.24,762.69 C64.1@196.24,839.32
1P8V: C49.1 C50.1 U4.11 | length 190.9
  Layer 1 - Top Layer w12: U4.11@354.06,759.86 354.06,700.26 C50.1@355.32,699 355.32,686.68 402.53,639.47 C49.1@453,639.47
1R: C65.1 R33.2 U4.4 | length 134.3
  Layer 1 - Top Layer w10: U4.4@216.26,759.86 216.26,791.74 v1(231,806.48)
  Layer 6 - Bottom Layer w10: C65.1@231,839.32 v1(231,806.48) 243,794.48 R33.2@243,762.69
2L: C62.1 R31.2 U4.1 | length 142
  Layer 1 - Top Layer w10: v1(126.72,806.48) 130.37,806.48 157.2,779.64 U4.1@157.2,759.86
  Layer 6 - Bottom Layer w10: R31.2@117,762.69 117,796.76 v1(126.72,806.48) C62.1@126.72,839.32
2R: C63.1 R35.2 U4.2 | length 129.6
  Layer 1 - Top Layer w10: v1(161.48,806.48) 176.89,791.07 U4.2@176.89,759.86
  Layer 6 - Bottom Layer w10: R35.2@161.48,762.69 v1(161.48,806.48) C63.1@161.48,839.32
3V3_1865A1: C47.1 C48.1 L25.1 U4.8 | length 274.1
  Layer 1 - Top Layer w12: C48.1@285.68,679 285.68,703.68 295,713 U4.8@295,759.86
  Layer 1 - Top Layer w20: v1(285,623) C48.1@285,678.32
  Layer 6 - Bottom Layer w20: v1(285,623) 285,564.53 C47.1@296,553.53 296.16,553.68 L25.1@356,553.68
3V3_1865D1: C44.1 C46.1 R24.1 U4.13 U4.14 | length 424.1
  Layer 1 - Top Layer w12: U4.13@393.43,759.86 393.43,794.43 404,805 472.32,805 C46.1@473,805.68 473,827.58 456.58,844 v1(398,844) ; U4.14@413.11,759.86 413.11,804.11
  Layer 6 - Bottom Layer w20: R24.1@317,903.84 317,878.54 322.53,873 358.47,873 C44.1@372.47,887 372.47,844.04 372.51,844 v1(398,844)
3V3_OUT: C67.1 C71.1 R40.2 U5.4 | length 102.7
  Layer 1 - Top Layer w12: C67.1@120.35,1393.83 154.83,1393.83 178.69,1417.69 U5.4@213.2,1417.69
+3P3V: C15.1 C41.1 C42.1 L25.2 R5.1 R7.2 R8.2 R12.1 R13.1 R15.2 R16.2 R17.2 R18.2 R21.2 R24.2 R26.2 R40.1 U1.19 U2.7 U2.8 U3.1 | length 5566.8
  Layer 1 - Top Layer w10: v1(292,1277) 309.69,1259.31 R26.2@309.69,1229
  Layer 1 - Top Layer w12: R16.2@1511.69,1130 1511.69,1165 1555,1165 v1(1565,1175) ; R17.2@1512.69,1094 R16.2@1512.69,1129 ; U3.1@1974.84,835.14 2015.54,835.14 C42.1@2016,834.68 v1(2016,870)
  Layer 1 - Top Layer w15: R12.1@1530,1509.69 v1(1555,1509.69) ; v1(1600,1509.37) R13.1@1625,1509.37 ; R21.2@2002.81,500.69 v1(2002.81,533.81)
  Layer 4 - PWR w30: v1(79,1257) v1(104.49,1257) 200.64,1257 220.64,1277 v1(292,1277) 508,1277 561,1330 561,1519 616,1574 1224,1574 1270,1528 v1(1270,1505) v1@1275,1505 ; v1@1275,1510 v1(1385,1510) v1(1425,1510) v1(1465,1510) ; v1@1465.31,1509.69 v1(1555,1509.69) 1555.31,1509.37 v1(1600,1509.37) 2016,1093.37 v1(2016,870) 1982,836 1982,740.75 1987,735.75 1987,549.62 v1(2002.81,533.81)
  Layer 3 - Sensitive w30: v1(79,1257) v1(104.49,1257) 243.78,1257 292,1208.78 292,995 v1(344,943) 358,929 358,720.73 439.71,639.03 439.71,504.71 390.69,455.69 v1(379.69,455.69) ; v1@1270,1499 1270,1460 1302.56,1427.44 v1(1302.56,1390) ; v1(1270,1505) 1380,1505 v1(1385,1510) ; v1@1554.69,1509.69 1554.69,1185.31 v1(1565,1175)
  Layer 6 - Bottom Layer w12: v1(1600,1509.37) 1650.63,1560 R18.2@1739.38,1560
  Layer 6 - Bottom Layer w15: U1.19@1282.5,1273.01 1282.5,1321.5 1298,1337 1298,1355.44 C15.1@1302.56,1360 v1(1302.56,1390) ; R5.1@1385,1439.68 v1(1385,1510) ; R8.2@1425,1439.69 v1(1425,1510) ; R7.2@1465,1439.69 v1(1465,1510)
  Layer 6 - Bottom Layer w20: L25.2@356,514.31 356,479.37 v1(379.69,455.69)
  Layer 6 - Bottom Layer w25: R24.2@317.41,942.8 317.62,943 v1(344,943)
AREF: C19.2 C21.2 U1.4 | length 354.6
  Layer 6 - Bottom Layer w12: U1.4@907.5,1273.01 907.5,1439.5 926,1458 926,1536 935.56,1545.56 C19.2@960,1545.56 C21.2@1006,1545.56
AVDD_GND: C24.2 U1.7 | length 174.2
  Layer 6 - Bottom Layer w12: U1.7@982.5,1273.01 982.5,1337.5 975,1345 975,1406.87 987.69,1419.56 C24.2@1007,1419.56
DOUT: TP8.1 U1.15 U4.18 | length 1237.9
  Layer 1 - Top Layer w8: v4(378,1112) TP8.1@378,1157 ; v4@379,1112 378,1111 378,1053 393.43,1037.57 U4.18@393.43,992.14
  Layer 3 - Sensitive w8: v4(378,1112) 512,978 676,978 776,1078 1131,1078 1182,1129 v1(1182,1204)
  Layer 6 - Bottom Layer w8: v1(1182,1204) 1182.5,1204.5 U1.15@1182.5,1273.01
DOUT2: TP9.1 U1.16 U4.21 | length 1275.2
  Layer 1 - Top Layer w8: U4.21@334.37,992.14 334.37,1037.63 348,1051.26 348,1080 348,1084.92 348,1090.83 v4(348,1112)
  Layer 3 - Sensitive w8: v4(348,1112) 500,960 692,960 781,1049 1150,1049 1207.5,1106.5 v1(1207.5,1177.5)
  Layer 6 - Bottom Layer w8: v1(1207.5,1177.5) U1.16@1207.5,1273.01
FR_L_ATTN: C52.1 R28.1 R36.2 | length 118.6
  Layer 1 - Top Layer w10: C52.1@239,495.47 213,469.47 R36.2@213,427.69 R28.1@253,427.68
FR_R_ATTN: C56.1 R32.1 R38.2 | length 113
  Layer 6 - Bottom Layer w10: C56.1@198,495.47 213,480.47 R38.2@213,427.69 R32.1@252,427.68
FRONT_L: J6.1 R9.1 R28.2 | length 390.2
  Layer 1 - Top Layer w10: R9.1@197,230.32 197,198 225,170 J6.1@274.04,170 325,220.96 325,316.31 R28.2@253,388.31
FRONT_R: J6.3 R10.1 R14.2 R32.2 | length 593.3
  Layer 6 - Bottom Layer w10: R10.1@197,227.32 325.68,227.32 374.04,178.96 J6.3@374.04,170 426,221.96 426,343 380.69,388.31 R32.2@252,388.31
FS: R15.1 U2.5 U3.10 | length 778.7
  Layer 1 - Top Layer w8: U2.5@1251.14,1211.61 1300.34,1211.61 R15.1@1302.48,1213.76 1326.59,1213.76 1346.28,1233.44 1536.26,1233.44 1586,1183.7 1586,1057.27 1744.53,898.74 U3.10@1744.53,835.14
GND: C1.2 C2.2 C3.2 C4.2 C5.2 C6.2 C7.2 C8.2 C9.2 C10.2 C11.2 C12.2 C13.2 C15.2 C17.2 C18.2 C22.2 C25.2 C26.2 C31.2 C32.2 C35.2 C36.2 C37.2 C38.2 C39.2 C40.2 C41.2 C42.2 C43.2 C44.2 C46.2 C47.2 C48.2 C49.2 C50.2 C51.2 C53.2 C54.2 C58.2 C59.2 C60.2 C61.2 C62.2 C63.2 C64.2 C65.2 C66.2 C67.2 C71.2 J4.5 J6.5 J6.6 J6.9 J6.10 J6.19 J6.20 MH1.1 MH2.1 R3.1 R6.2 R27.1 R36.1 R37.1 R38.1 R39.1 S1.2 U1.1 U1.11 U1.17 U1.18 U1.23 U1.28 U1.33 U1.36 U1.39 U1.46 U1.49 U1.52 U2.2 U2.3 U2.4 U3.20 U4.7 U4.12 U4.15 U4.26 U5.7 U5.8 U5.9 U5.10 U5.11 U5.12 U5.13 U5.14 U5.21 Y1.2 Y1.4 | length 1878.2
  Layer 1 - Top Layer w10: C48.2@246.31,679 246.31,692.31 275.31,721.31 U4.7@275.31,759.86 ; U4.12@373.74,759.86 373.74,724.26 394.69,703.31 C50.2@394.69,699 ; U4.15@432.8,759.86 466.54,759.86 C46.2@473,766.31
  Layer 1 - Top Layer w12: C60.2@137,1110.69 v1(137,1147) ; C58.2@169,1110.69 v1(169,1147) ; C61.2@201,1110.69 v1(201,1147) ; U4.26@235.94,992.14 235.94,961.06 265,932 v1(265,921) ; Y1.2@367.52,557.61 367.52,599.17 366.31,600.37 387,600.37 388,599.37 v1(388,585) ; C50.2@394.69,699 395.16,698.53 453,698.53 455,700.53 v1(455,737) ; Y1.4@432.48,508.39 438.4,514.31 C53.2@474,514.31 ; C46.2@473,766.31 480.49,758.83 v1(480.49,737) ; C43.2@1967.81,500.69 1967.81,561.81 1974.84,568.84 U3.20@1974.84,602.86
  Layer 1 - Top Layer w15: v1@800.32,1289.68 830,1289.68 ; v1(1200.31,1539.69) 1235,1539.69
  Layer 1 - Top Layer w20: v1(2014,759) 2016,761 C42.2@2016,795.31
  Layer 6 - Bottom Layer w12: C62.2@126.72,878.69 v1@126.72,920.28 ; C63.2@161.48,878.69 v1@161.48,920.52 ; C64.2@196.24,878.69 v1@196.24,920.24 ; C65.2@231,878.69 v1@231,920
  Layer 6 - Bottom Layer w15: U1.52@932.5,898.99 932,899.49 932,1002 932.5,1002.5 ; U1.49@1007.5,898.99 1007,899.49 1007,1002 1007.5,1002.5 ; U1.46@1082.5,898.99 1082,899.49 1082,1002 1082.5,1002.5 ; v1(1082.5,1205) U1.11@1082.5,1273.01 ; R3.1@1089.68,1475 1090,1475.32 v1(1090,1495) ; U1.39@1257.5,898.99 1257,899.49 1257,997 1257.5,997.5 ; U1.36@1332.5,898.99 1332,899.49 1332,1002 1332.5,1002.5 ; R6.2@1345,1439.69 v1(1345,1465) ; v1(1382.5,1212) U1.23@1382.5,1273.01 ; U1.33@1407.5,898.99 1407,899.49 1407,1002 1407.5,1002.5 ; v1(1507.5,1212) U1.28@1507.5,1273.01
  other v1: 50,50 217.5,50 385,50 552.5,50 720,50 887.5,50 1055,50 1222.5,50 1390,50 1557.5,50 1725,50 1892.5,50 2060,50 50,119 2060,210.14 50,279.14 186,302 370,338 220,361 2057,370.29 710,401 741,401 1119,401 1144,401 1169,401 1194,401 1221,401 1599,401 710,426 741,426 1094,426 1119,426 1144,426 1169,426 1196,426 1221,426 1246,426 1574,426 1599,426 1624,426 335,429 47,439.29 710,451 1144,451 1169,451 1196,451 1624,451 710,476 1144,476 1169,476 1196,476 1624,476 1144,501 1169,501 1196,501 2057,530.43 47,599.43 171,606 253,606 700,660 725,660 750,660 1590,660 1615,660 1640,660 126,673 700,685 725,685 750,685 1590,685 1615,685 1640,685 700,710 725,710 750,710 1590,710 1615,710 1640,710 775,755 1565,755 47,759.57 775,780 800,780 1540,780 1565,780 2057,850.71 47,919.71 126,921 161,921 197,921 230,921 932,970 1007,970 1082,970 1257,970 1332,970 1407,970 2055,1010.86 45,1079.86 239,1143 2055,1171 750,1215 775,1215 800,1215 45,1228 750,1240 775,1240 800,1240 556,1241 581,1241 606,1241 800,1265 800,1290 144,1292 169,1292 800,1315 169,1317 2055,1334 1235,1390 1260,1390 1235,1415 1260,1415 2055,1483 301,1486 326,1486 351,1486 45,1502 301,1515 326,1515 351,1515 45,1615 380,1615 547.5,1615 715,1615 882.5,1615 1050,1615 1217.5,1615 1385,1615 1552.5,1615 1720,1615 1887.5,1615 2055,1615
  other v2: 586,1014.64 1754,1014.64 524.2,1050.32 647.8,1050.32 1692.2,1050.32 1815.8,1050.32 524.2,1121.68 647.8,1121.68 1692.2,1121.68 1815.8,1121.68 586,1157.36 1754,1157.36
  other v3: 307.69,1336 351,1336 307.69,1379.31 351,1379.31 307.69,1422.61 351,1422.61
I2C_A0: R5.2 R6.1 U1.22 | length 178.7
  Layer 6 - Bottom Layer w8: R6.1@1345,1400.32 R5.2@1385,1400.31 1385,1375 1357.5,1347.5 U1.22@1357.5,1273.01
I2S_ADSEL_1865_1: R26.1 R27.2 U4.25 | length 243.5
  Layer 1 - Top Layer w8: U4.25@255.63,992.14 255.63,1027.26 271,1042.63 271,1159.69 270.69,1160 R27.2@270.69,1195 270.69,1228.63 R26.1@270.32,1229
LRCLK: TP11.1 U1.14 U4.16 | length 1132.4
  Layer 1 - Top Layer w8: U4.16@432.8,992.14 432.8,1027 450,1044.2 450,1100 v4(438,1112) TP11.1@438,1156
  Layer 3 - Sensitive w8: v4(438,1112) 438,1167 464.46,1193.46 635.54,1193.46 717,1112 1117,1112 1157.5,1152.5 v1(1157.5,1175)
  Layer 6 - Bottom Layer w8: v1(1157.5,1175) U1.14@1157.5,1273.01
MCLK: TP1.1 U1.12 U2.6 | length 285.7
  Layer 1 - Top Layer w8: TP1.1@1125,1370.98 1125,1366.06 1125,1360.16 v1(1125,1340) 1125,1320 1207.8,1237.2 U2.6@1251.14,1237.2
  Layer 6 - Bottom Layer w8: U1.12@1107.5,1273.01 1107.5,1322.5 v1(1125,1340)
NetC14_2: C14.2 U1.54
NetC16_2: C16.2 U1.50
NetC19_1: C19.1 U1.5 | length 228.8
  Layer 6 - Bottom Layer w12: U1.5@932.5,1273.01 932.5,1430.5 960,1458 C19.1@960,1490.44
NetC20_2: C20.2 U1.48
NetC21_1: C21.1 U1.6 | length 249.1
  Layer 6 - Bottom Layer w12: U1.6@957.5,1273.01 956,1274.51 956,1427 977.31,1448.31 995,1448.31 1006,1459.31 C21.1@1006,1490.44
NetC23_2: C23.2 U1.44
NetC24_1: C24.1 U1.8 | length 103.4
  Layer 6 - Bottom Layer w8: C24.1@1006.56,1376 1007.5,1375.06 U1.8@1007.5,1273.01
NetC27_2: C27.2 U1.41
NetC28_1: C28.1 U1.9 | length 111.7
  Layer 6 - Bottom Layer w8: U1.9@1032.5,1273.01 1032.5,1332.5 1050,1350 C28.1@1050,1377.44
NetC28_2: C28.2 C29.2 R3.2 | length 97.6
  Layer 6 - Bottom Layer w8: R3.2@1050.31,1475 1050,1474.69 C28.2@1050,1432.56 C29.2@1105,1432.56
NetC29_1: C29.1 U1.10 | length 138.8
  Layer 6 - Bottom Layer w8: U1.10@1057.5,1273.01 1057.5,1327.5 1070,1340 1095,1340 1105,1350 C29.1@1105,1377.44
NetC30_2: C30.2 U1.37
NetC33_2: C33.2 U1.35
NetC34_2: C34.2 U1.31
NetC51_1: C51.1 U4.6 | length 97.7
  Layer 1 - Top Layer w10: C51.1@202.56,700.56 202.84,700.84 230.8,700.84 255.63,725.67 U4.6@255.63,759.86
NetC52_2: C52.2 R29.1 | length 178.9
  Layer 1 - Top Layer w10: v1(196,642) 224,614 224,569.53 C52.2@239,554.53
  Layer 6 - Bottom Layer w10: v1@196.24,649.74 R29.1@196.24,723.32
NetC55_2: C55.2 R31.1 | length 194.6
  Layer 1 - Top Layer w10: v1(96,642) 96,576.53 C55.2@118,554.53
  Layer 6 - Bottom Layer w10: v1(96,642) 96,716 103.32,723.32 R31.1@117,723.32
NetC56_2: C56.2 R33.1 | length 198.9
  Layer 6 - Bottom Layer w10: C56.2@198,554.53 217.53,554.53 220,557 220,607 231,618 231,671 243,683 R33.1@243,723.32
NetC57_2: C57.2 R35.1 | length 186.8
  Layer 6 - Bottom Layer w10: C57.2@118,554.53 121,557.53 121,609.62 161.48,650.1 R35.1@161.48,723.32
NetC58_1: C58.1 U4.29 | length 82.4
  Layer 1 - Top Layer w8: C58.1@169,1071.32 169,1035 176.89,1027.11 U4.29@176.89,992.14
NetC59_1: C59.1 U4.27 | length 86.1
  Layer 1 - Top Layer w8: U4.27@216.26,992.14 216.26,1024.26 232,1040 232,1070.32 C59.1@233,1071.32
NetC60_1: C60.1 U4.30 | length 87.5
  Layer 1 - Top Layer w8: C60.1@137,1071.32 137,1035 157.2,1014.8 U4.30@157.2,992.14
NetC61_1: C61.1 U4.28 | length 81
  Layer 1 - Top Layer w10: U4.28@196.57,992.14 196.57,1029.57 201,1034 C61.1@201,1071.32
NetC66_1: C66.1 U5.3 | length 61.6
  Layer 1 - Top Layer w8: C66.1@152.03,1444.31 153.06,1443.28 U5.3@213.2,1443.28
NetD1_2: D1.2 R12.2 | length 38.8
  Layer 1 - Top Layer w8: D1.2@1530,1431.5 R12.2@1530,1470.32
NetD2_2: D2.2 R13.2 | length 38.8
  Layer 1 - Top Layer w8: D2.2@1625,1431.5 R13.2@1625,1470.32
NetJ4_2: J4.2 R18.1 | length 113.3
  Layer 6 - Bottom Layer w12: R18.1@1786.62,1560 1786.62,1527.38 1797,1517 J4.2@1797,1451
NFAULT1: D1.1 J6.34 U1.26 U3.8 | length 1417.8
  Layer 1 - Top Layer w8: D1.1@1530,1368.5 1526.5,1365 v1(1495,1365) 1495,1319 1623,1191 1623,1053 1795.71,880.29 U3.8@1795.71,835.14 1795.71,777.71 v1(1780,762)
  Layer 6 - Bottom Layer w8: U1.26@1457.5,1273.01 1457.5,1342.5 1480,1365 v1(1495,1365) ; v1(1780,762) 1780,371 1874.04,276.96 J6.34@1874.04,270
NMUTE: J6.30 R7.1 U1.25 | length 1346.5
  Layer 3 - Sensitive w8: v1(1410,1195) 1368,1153 1368,1083 1447,1004 1447,890 1523.81,813.19 1607.89,813.19 1674.04,747.04 J6.30@1674.04,270
  Layer 6 - Bottom Layer w8: v1(1410,1195) 1432.5,1217.5 U1.25@1432.5,1273.01 1432.5,1347.5 1465,1380 R7.1@1465,1400.32
NRST_TDIO: C43.1 J4.4 R21.1 S1.1 U3.16 | length 1134.4
  Layer 1 - Top Layer w8: v1(1872.48,686.52) U3.16@1872.48,602.86 1872.48,566.87 1905.68,533.68 S1.1@1905.68,457 1963.5,457 C43.1@1967.81,461.32 R21.1@2002.81,461.32
  Layer 3 - Sensitive w8: v1(1852,1335) 1872,1315 1872,687 v1(1872.48,686.52)
  Layer 6 - Bottom Layer w8: v1(1852,1335) 1853,1335 1897,1379 J4.4@1897,1451
NSTANDBY: J6.29 R8.1 U1.24 U3.11 | length 1995.2
  Layer 1 - Top Layer w8: v1(1726,559) 1744,559 1744.53,559.53 U3.11@1744.53,602.86
  Layer 3 - Sensitive w8: v1(1395,1345) 1318.1,1268.1 1318.1,1049.9 1372,996 1372,765 1529.04,607.96 1529.04,367 1560.04,336 1600,336 1627,309 1627,217.04 J6.29@1674.04,170
  Layer 6 - Bottom Layer w8: U1.24@1407.5,1273.01 1407.5,1332.5 v1(1395,1345) 1395,1347.5 1425,1377.5 R8.1@1425,1400.32 ; J6.29@1674.04,170 1726,221.96 v1(1726,559)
